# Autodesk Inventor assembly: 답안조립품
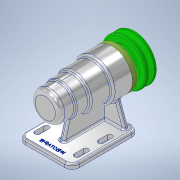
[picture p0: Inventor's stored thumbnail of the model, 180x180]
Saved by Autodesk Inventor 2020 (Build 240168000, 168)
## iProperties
Created: 2021-10
Part Number: 답안조립품
Document SubType Name: Assembly
Designer: user
Author: user
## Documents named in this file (12)
- C:\Users\user\Desktop\711007V1011\답안조립품.iam
- C:\Users\user\Desktop\711007V1011\V벨트풀리.ipt
- C:\Users\user\Desktop\711007V1011\멈춤나사 M3.ipt
- C:\Users\user\Desktop\711007V1011\베어링 6004.ipt
- C:\Users\user\Desktop\711007V1011\베어링 51202.ipt
- C:\Users\user\Desktop\711007V1011\본체.ipt
- C:\Users\user\Desktop\711007V1011\볼트 M4.ipt
- C:\Users\user\Desktop\711007V1011\어댑터슬리브.ipt
- C:\Users\user\Desktop\711007V1011\오일 실 20x35x7.ipt
- C:\Users\user\Desktop\711007V1011\축.ipt
- C:\Users\user\Desktop\711007V1011\커버.ipt
- C:\Users\user\Desktop\711007V1011\키 5x5.ipt
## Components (1 placed, 1 different names)
1. V벨트풀리:1
